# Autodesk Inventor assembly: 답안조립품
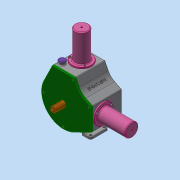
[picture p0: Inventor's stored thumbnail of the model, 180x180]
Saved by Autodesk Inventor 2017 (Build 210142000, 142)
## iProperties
Part Number: 답안조립품
Material: 일반
Document SubType Name: Assembly
Designer: MRC
Mass: 3748.67 g
Surface Area: 4101.75 cm^2
Volume: 1119.43 cm^3
Density: 3.34872 g/cm^3
Author: MRC
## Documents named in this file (13)
- C:\Users\MRC\Desktop\611109V1006\답안조립품.iam
- C:\Users\MRC\Desktop\611109V1006\본체.ipt
- C:\Users\MRC\Desktop\611109V1006\너트 M3.ipt
- C:\Users\MRC\Desktop\611109V1006\베어링 20 x 37 x 9.ipt
- C:\Users\MRC\Desktop\611109V1006\볼트 M3 x 12.ipt
- C:\Users\MRC\Desktop\611109V1006\실린더.ipt
- C:\Users\MRC\Desktop\611109V1006\앞커버.ipt
- C:\Users\MRC\Desktop\611109V1006\축.ipt
- C:\Users\MRC\Desktop\611109V1006\측정게이지.ipt
- C:\Users\MRC\Desktop\611109V1006\커넥팅로드 캡.ipt
- C:\Users\MRC\Desktop\611109V1006\커넥팅로드.ipt
- C:\Users\MRC\Desktop\611109V1006\피스톤 핀.ipt
- C:\Users\MRC\Desktop\611109V1006\피스톤.ipt
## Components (4 placed, 2 different names)
1. 피스톤 핀:1
2. 피스톤:1
3. 피스톤:2
4. 피스톤 핀:2
